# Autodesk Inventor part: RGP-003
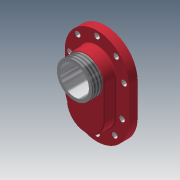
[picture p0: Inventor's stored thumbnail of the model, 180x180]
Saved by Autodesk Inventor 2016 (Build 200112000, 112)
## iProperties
Created: 2013-11
Part Number: RGP-003
Material: Aluminum 6061
Document SubType Name: Modeling
Designer: normanpa
Density: 2.71 g/cm^3
Appearance: 255,61,77
Description: FRONT COVER
Mass: 971.676 g
Surface Area: 684.974 cm^2
Volume: 358.552 cm^3
Author: Autodesk
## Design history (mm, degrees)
workplane "Work Plane1"
sketch "Sketch1"
  geometry: L1 (-60, 55.151)-(-60, -4.849); L2 (60, -4.849)-(60, 55.151); C1 r 5 at (-47, -4.849); C2 r 5 at (50.721, 55.151) reference; C3 r 5 at (50.721, 55.151) reference; A1 r 60 centre (0, 55.151) between (60, 55.151) and (-60, 55.151); A2 r 60 centre (0, -4.849) between (-60, -4.849) and (60, -4.849); 1 further point
  constraints: 5 centre point, 4 end point, 4 point on circle, 4 other
extrude "Extrusion1" new body sketch "Sketch1" distance "d0" = 16; taper "d1" = 0 deg
sketch "Sketch2"
  geometry: L1 (-60, 55.151)-(-60, -4.849) reference; L2 (60, -4.849)-(60, 55.151) reference; L3 (35, 55.151)-(35, -4.849); L4 (-35, -4.849)-(-35, 55.151); A1 r 60 centre (0, 55.151) between (60, 55.151) and (-60, 55.151) reference; A2 r 60 centre (0, -4.849) between (-60, -4.849) and (60, -4.849) reference; A3 r 35 centre (0, 55.151) between (35, 55.151) and (-35, 55.151); A4 r 35 centre (0, -4.849) between (-35, -4.849) and (35, -4.849); 1 further point
  constraints: 4 end point, 4 point on circle, 2 centre point, 3 other
  dimensions: "d2" = 35 radius of A3
extrude "Extrusion2" join sketch "Sketch2" distance "d3" = 22; taper "d4" = 0 deg
fillet "Fillet1" dims "d5" = 2
hole "Hole1" sketch "Sketch1" diameter "d6" = 10; stored, may be unused: countersink angle "d10" = 90 deg, drill point angle "d12" = 118 deg; dims "d7" = 6, "d8" = 4, "d9" = 2, "d11" = 8
hole "Hole2" sketch "Sketch1" diameter "d13" = 10; stored, may be unused: countersink angle "d17" = 90 deg, drill point angle "d19" = 118 deg; dims "d14" = 6, "d15" = 4, "d16" = 2, "d18" = 8
pattern_circular "Circular Pattern1" dims angle "d21" = 180 deg
pattern_circular "Circular Pattern2" dims angle "d24" = 180 deg
sketch "Sketch3"
  geometry: 1 further point
hole "Hole3" diameter "d26" = 40; stored, may be unused: countersink angle "d30" = 90 deg, drill point angle "d32" = 0 deg; dims "d27" = 6, "d28" = 4, "d29" = 2, "d31" = 30, "d46" = 10, "d47" = 10
sketch "Sketch4"
  geometry: C1 r 33 at (0, 55.151); A1 r 35 centre (0, 55.151) between (35, 55.151) and (-35, 55.151) reference; 1 further point
  constraints: 1 centre point, 1 coincident
  dimensions: "d33" = 66 diameter of C1
extrude "Extrusion3" join sketch "Sketch4" distance "d34" = 20; taper "d35" = 0 deg
hole "Hole4" diameter "d38" = 54; stored, may be unused: countersink angle "d42" = 90 deg, drill point angle "d44" = 118 deg; dims "d36" = 10, "d37" = 10, "d39" = 6, "d40" = 4, "d41" = 2, "d43" = 8
fillet "Fillet2" dims "d45" = 2
thread "Thread1" dims "d48" = 10, "d49" = 0
body "Solid1"
